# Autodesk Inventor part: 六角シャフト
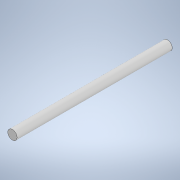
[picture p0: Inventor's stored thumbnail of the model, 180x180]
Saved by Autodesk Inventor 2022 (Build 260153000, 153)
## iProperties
Created: 2024-12
Part Number: 六角シャフト
Material: 一般
Document SubType Name: Modeling
Designer: jsat7
Density: 1 g/cm^3
Appearance: 既定
Author: jsat7
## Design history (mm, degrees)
sketch "スケッチ1"
  geometry: C1 r 1.5 at (0, 0); 1 further point
  constraints: 1 centre point, 1 coincident
  dimensions: "d0" = 3 diameter of C1
extrude "押し出し1" new body sketch "スケッチ1" distance "d1" = 50; taper "d2" = 0 deg
node "ソリッド1"
